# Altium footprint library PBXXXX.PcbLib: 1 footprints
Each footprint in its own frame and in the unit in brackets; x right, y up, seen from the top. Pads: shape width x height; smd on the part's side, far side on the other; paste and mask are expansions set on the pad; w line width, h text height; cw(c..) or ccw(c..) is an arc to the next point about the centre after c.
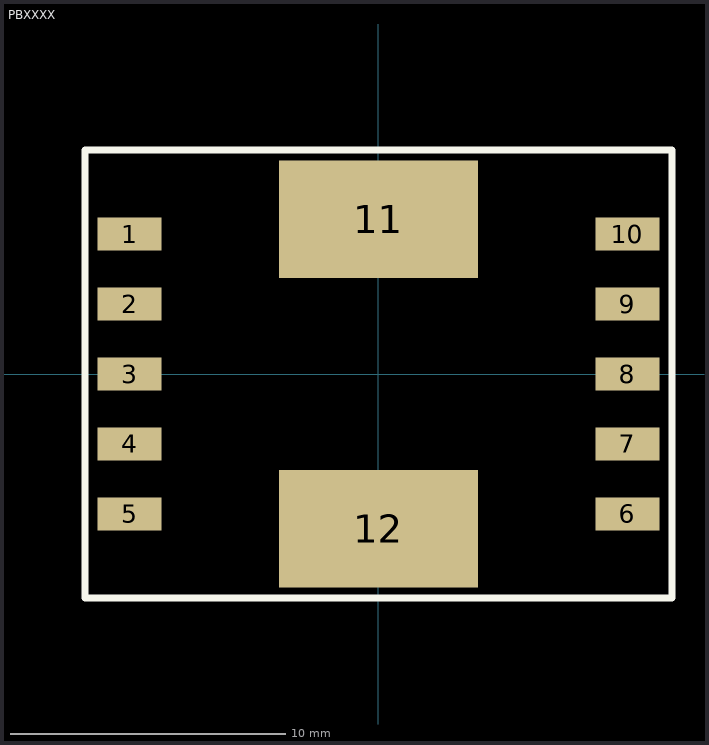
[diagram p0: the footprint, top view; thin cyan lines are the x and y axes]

## PBXXXX [mil] "PULSE PBXXXX TRANSFORMER"
height 394
pads (13):
  round 60 on Top Overlay: 0(-460,200)
  rect 92x47 smd: 1(-356,200) 2(-356,100) 3(-356,0) 4(-356,-100) 5(-356,-200) 6(356,-200) 7(356,-100) 8(356,0) 9(356,100) 10(356,200)
  rect 285x167.5 smd: 11(0,221.25) 12(0,-221.25)
Top Overlay:
  lines w10: -420,-320 420,-320 420,320 -420,320 -420,-320
M5 Assembly Top:
  text ".Designator" at 0,0 h40
3D body: height 394, standoff 0, extent -420,-320 420,320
